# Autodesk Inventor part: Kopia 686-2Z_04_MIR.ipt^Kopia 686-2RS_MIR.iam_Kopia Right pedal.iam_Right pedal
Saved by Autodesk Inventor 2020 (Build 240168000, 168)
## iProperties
Created: 2017-10
Part Number: Kopia 686-2Z_04_MIR.ipt^Kopia 686-2RS_MIR.iam_Kopia Right pedal.iam_Right pedal
Material: Ogólny
Document SubType Name: Modeling
Designer: Tomasz
Density: 1 g/cm^3
Appearance: Domyślna
Sending System: SolidWorks 2017
Last Author: Tomasz
Last Saved: 2017-10-01
Author: Tomasz
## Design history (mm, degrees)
